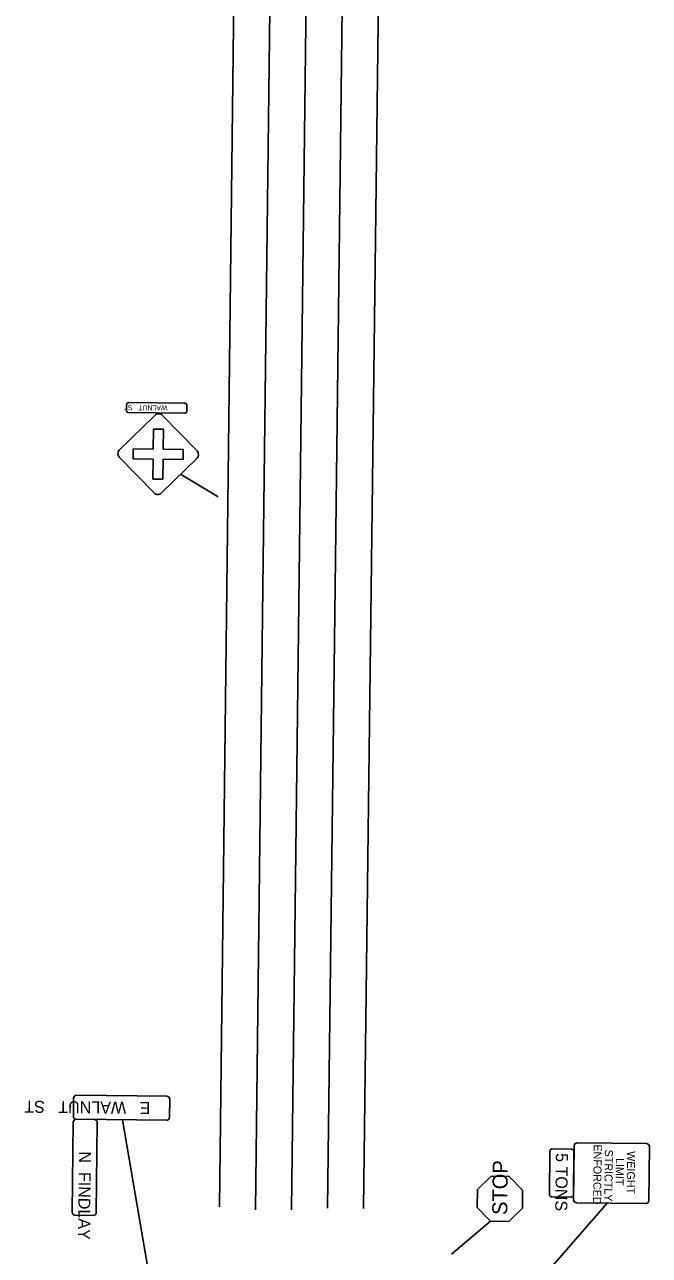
# Model space of a CAD drawing. Extents: x 1652376 to 1652707, y 605933 to 608571.
# Drawn here: x 1652464.2 to 1652672.1, y 607285.1 to 607695.1 of the extents above; entities that cross this region are included whole.
import ezdxf

# ---------------------------------------------------------------- set-up
doc = ezdxf.new("R2010")
doc.units = 0
for name, color, linetype in [('GE_P_Alignment', 7, 'Continuous'), ('PM_P_CL_Double_Solid', 7, 'Continuous'), ('PV_P_EOP', 7, 'Continuous'), ('SH_Border', 7, 'Continuous'), ('SN_P_Text', 7, 'Continuous'), ('UT_X_Misc_Cells', 7, 'Continuous')]:
    doc.layers.add(name, color=color, linetype=linetype)

msp = doc.modelspace()

# ---------------------------------------------------------------- linework, layer by layer
at = {"layer": 'GE_P_Alignment'}
for points in [[(1652540.98, 607300.27), (1652543.38, 607498.25), (1652555.8, 608525.74)], [(1652564.99, 607300.89), (1652567.39, 607498.86), (1652579.8, 608525.7)]]:
    msp.add_lwpolyline(points, dxfattribs=at)
at = {"layer": 'PM_P_CL_Double_Solid'}
for p, q in [((1652528.99, 607301.33), (1652543.79, 608525.88)), ((1652576.99, 607300.75), (1652591.91, 608525.32))]:
    msp.add_line(p, q, dxfattribs=at)
at = {"layer": 'PV_P_EOP'}
msp.add_line((1652552.98, 607300.25), (1652567.79, 608525.6), dxfattribs=at)
at = {"layer": 'SH_Border'}
for p, q in [((1652507.05, 607560.39), (1652506.97, 607553.72)), ((1652510.38, 607560.35), (1652507.05, 607560.39)), ((1652510.31, 607553.68), (1652510.38, 607560.35)), ((1652500.31, 607553.79), (1652500.27, 607550.46)), ((1652500.27, 607550.46), (1652506.94, 607550.39)), ((1652506.97, 607553.72), (1652500.31, 607553.79)), ((1652506.94, 607550.39), (1652506.86, 607543.72)), ((1652510.2, 607543.68), (1652510.27, 607550.35)), ((1652510.27, 607550.35), (1652516.94, 607550.28)), ((1652516.97, 607553.61), (1652510.31, 607553.68)), ((1652516.94, 607550.28), (1652516.97, 607553.61)), ((1652506.86, 607543.72), (1652510.2, 607543.68)), ((1652639.78, 607320.59), (1652646.18, 607320.52)), ((1652638.81, 607305.4), (1652638.97, 607319.8)), ((1652646.97, 607319.71), (1652646.81, 607305.31)), ((1652619.42, 607311.52), (1652614.87, 607307.07)), ((1652625.42, 607311.45), (1652619.42, 607311.52)), ((1652629.87, 607306.9), (1652625.42, 607311.45)), ((1652614.87, 607307.07), (1652614.81, 607301.07)), ((1652629.81, 607300.9), (1652629.87, 607306.9)), ((1652646.01, 607304.52), (1652639.61, 607304.59)), ((1652614.81, 607301.07), (1652619.26, 607296.52)), ((1652625.26, 607296.45), (1652629.81, 607300.9)), ((1652619.26, 607296.52), (1652625.26, 607296.45))]:
    msp.add_line(p, q, dxfattribs=at)
for points in [[(1652498.15, 607568.57), (1652498.13, 607566.49)], [(1652517.53, 607568.98), (1652498.78, 607569.19)], [(1652518.13, 607566.27), (1652518.15, 607568.35)], [(1652507.59, 607565.01), (1652495.67, 607553.35)], [(1652498.75, 607565.86), (1652517.5, 607565.65)], [(1652521.6, 607553.07), (1652509.94, 607564.98)], [(1652495.65, 607551), (1652507.3, 607539.08)], [(1652509.66, 607539.06), (1652521.57, 607550.71)], [(1652480.42, 607331.49), (1652480.48, 607337.49)], [(1652511.49, 607338.15), (1652481.49, 607338.48)], [(1652512.41, 607331.14), (1652512.48, 607337.14)], [(1652480.39, 607329.49), (1652480.06, 607299.49)], [(1652487.4, 607330.41), (1652481.4, 607330.48)], [(1652481.4, 607330.48), (1652511.4, 607330.15)], [(1652488.06, 607299.4), (1652488.39, 607329.4)], [(1652646.87, 607303.65), (1652647.07, 607321.65)], [(1652648.08, 607322.64), (1652671.08, 607322.39)], [(1652672.07, 607321.37), (1652671.87, 607303.38)], [(1652670.86, 607302.39), (1652647.86, 607302.64)], [(1652487.05, 607298.42), (1652481.05, 607298.48)]]:
    msp.add_lwpolyline(points, dxfattribs=at)
for centre, radius, start, end in [((1652498.75, 607566.48), 0.625, 179.3709, 269.3709), ((1652498.78, 607568.57), 0.625, 89.3709, 179.3709), ((1652517.5, 607566.28), 0.625, 269.3709, 359.3709), ((1652517.52, 607568.36), 0.625, 359.3709, 89.3709), ((1652508.75, 607563.82), 1.67, 44.3709, 134.3709), ((1652496.84, 607552.16), 1.67, 134.3709, 224.3709), ((1652520.41, 607551.9), 1.67, 314.3709, 44.3709), ((1652508.49, 607540.25), 1.67, 224.3709, 314.3709), ((1652481.48, 607337.48), 1, 89.3709, 179.3709), ((1652511.48, 607337.15), 1, 359.3709, 89.3709), ((1652481.39, 607329.48), 1, 89.3709, 179.3709), ((1652481.42, 607331.48), 1, 179.3709, 269.3709), ((1652487.39, 607329.41), 1, 359.3709, 89.3709), ((1652511.41, 607331.15), 1, 269.3709, 359.3709), ((1652639.77, 607319.79), 0.8, 89.3709, 179.3709), ((1652646.17, 607319.72), 0.8, 359.3709, 89.3709), ((1652648.07, 607321.64), 1, 89.3709, 179.3709), ((1652671.07, 607321.39), 1, 359.3709, 89.3709), ((1652639.61, 607305.39), 0.8, 179.3709, 269.3709), ((1652646.01, 607305.32), 0.8, 269.3709, 359.3709), ((1652647.87, 607303.64), 1, 179.3709, 269.3709), ((1652670.87, 607303.39), 1, 269.3709, 359.3709), ((1652481.06, 607299.48), 1, 179.3709, 269.3709), ((1652487.06, 607299.42), 1, 269.3709, 359.3709)]:
    msp.add_arc(centre, radius, start, end, dxfattribs=at)
at = {"layer": 'UT_X_Misc_Cells'}
for p, q in [((1652516.04, 607545.3), (1652528.65, 607537.85)), ((1652496.77, 607330.31), (1652511.74, 607242.51)), ((1652658.08, 607302.53), (1652605.21, 607241.95)), ((1652619.26, 607296.52), (1652606.23, 607285.54))]:
    msp.add_line(p, q, dxfattribs=at)

# ---------------------------------------------------------------- texts
at = {"layer": 'SH_Border'}
for s, height, rotation, p in [('        WALNUT   ST', 1.6665, 179.3709, (1652516.87, 607568.16)), ('        E   WALNUT   ST', 4, 179.3709, (1652517.92, 607336.08)), ('        N  FINDLAY ', 4, 269.3709, (1652482.42, 607331.67)), ('STOP', 5, 89.3709, (1652624.78, 607298.59)), ('5 TONS', 4, 269.3709, (1652640.97, 607319.21))]:
    msp.add_text(s, height=height, rotation=rotation, dxfattribs=at).set_placement(p)
at = {"layer": 'SN_P_Text'}
for s, p in [('ENFORCED', (1652653.57, 607322.1)), ('STRICTLY', (1652657.26, 607320.37)), ('LIMIT', (1652660.95, 607317.58)), ('WEIGHT', (1652664.69, 607319.86))]:
    msp.add_text(s, height=2.667, rotation=269.3709, dxfattribs=at).set_placement(p)

doc.saveas('drawing.dxf')
